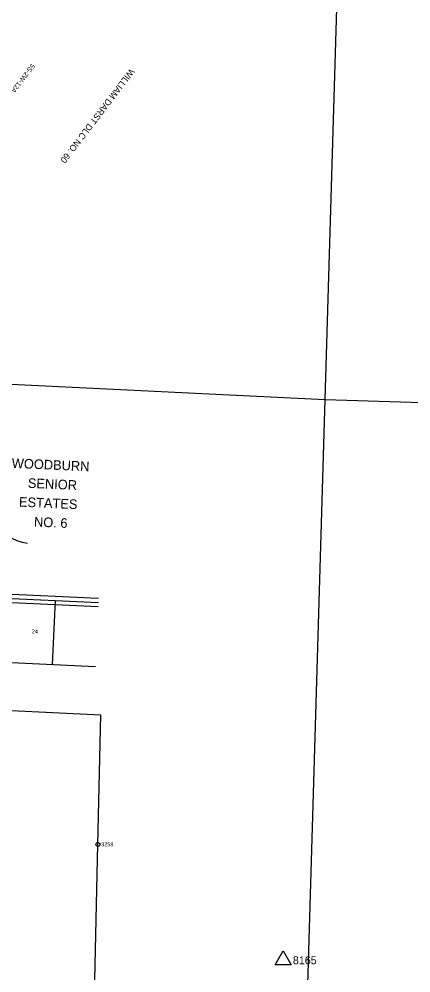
# Model space of a CAD drawing. Extents: x 7581380 to 7602708, y 543740 to 556109.
# Drawn here: x 7590534 to 7591024, y 550879 to 552072 of the extents above; entities that cross this region are included whole.
import ezdxf

# ---------------------------------------------------------------- set-up
doc = ezdxf.new("R2010")
doc.units = 0
for name, color, linetype in [('E_SURV_BNDRY_CROW', 7, 'Continuous'), ('E_SURV_BNDRY_Easement', 7, 'Continuous'), ('E_SURV_BNDRY_GovDLCLineTx', 7, 'Continuous'), ('E_SURV_BNDRY_GovSixSectLine', 7, 'Continuous'), ('E_SURV_BNDRY_Property', 7, 'Continuous'), ('E_SURV_BNDRY_SubdivisionTx', 7, 'Continuous'), ('E_Surv_Bndry_Tax_Lot', 7, 'Continuous'), ('E_SURV_MON_FdMon', 7, 'Continuous'), ('E_SURV_MON_FdMonTx', 7, 'Continuous'), ('E_SURV_NTW_SetNtwPt', 7, 'Continuous'), ('E_SURV_NTW_SetNtwPtTx', 7, 'Continuous')]:
    doc.layers.add(name, color=color, linetype=linetype)

msp = doc.modelspace()

# ---------------------------------------------------------------- linework, layer by layer
at = {"layer": 'E_SURV_BNDRY_CROW'}
for p, q in [((7590420.3, 551272.2), (7590629.5, 551262.4)), ((7590328.9, 551216.5), (7590636.5, 551201.9)), ((7590632.7, 551039.9), (7590636.5, 551201.9))]:
    msp.add_line(p, q, dxfattribs=at)
msp.add_arc((7590549.7, 551466.5), 50.2, 140.2086, 264.2644, dxfattribs=at)
at = {"layer": 'E_SURV_BNDRY_Easement'}
for p, q in [((7590633.5, 551347.3), (7590434.2, 551356.6)), ((7590433.8, 551346.7), (7590633.1, 551337.3))]:
    msp.add_line(p, q, dxfattribs=at)
at = {"layer": 'E_SURV_BNDRY_GovSixSectLine'}
for p, q in [((7588277.4, 551724.3), (7590917, 551595.9)), ((7590917, 551595.9), (7592227.2, 551558.5))]:
    msp.add_line(p, q, dxfattribs=at)
for points in [[(7590917, 551595.9), (7590956.2, 552910)], [(7590878.1, 550287.8), (7590917, 551595.9)]]:
    msp.add_lwpolyline(points, dxfattribs=at)
at = {"layer": 'E_SURV_BNDRY_Property'}
for p, q in [((7590424, 551352.1), (7590633.3, 551342.3)), ((7590576.1, 551264.9), (7590579.8, 551344.8)), ((7590613.5, 550215.1), (7590632.7, 551039.9))]:
    msp.add_line(p, q, dxfattribs=at)
at = {"layer": 'E_SURV_MON_FdMon'}
msp.add_circle((7590632.7, 551039.9), 2.5, dxfattribs=at)
at = {"layer": 'E_SURV_NTW_SetNtwPt'}
for p, q in [((7590854.5, 550889.3), (7590864.5, 550906.7)), ((7590864.5, 550906.7), (7590874.5, 550889.3)), ((7590874.5, 550889.3), (7590854.5, 550889.3)), ((7590864.5, 550895.1), (7590864.5, 550895.1))]:
    msp.add_line(p, q, dxfattribs=at)

# ---------------------------------------------------------------- texts
at = {"layer": 'E_SURV_BNDRY_GovDLCLineTx'}
msp.add_text('WILLIAM DARST DLC NO. 60', height=8, rotation=232.6004, dxfattribs=at).set_placement((7590672.9, 552010.2))
at = {"layer": 'E_SURV_BNDRY_SubdivisionTx'}
for s, height, rotation, p in [('WOODBURN', 12, 357.4657, (7590524.8, 551510.6)), ('SENIOR', 12, 357.4657, (7590544.9, 551485.7)), ('ESTATES', 12, 357.4657, (7590533.8, 551462.2)), ('NO. 6', 12, 357.4657, (7590552.6, 551437.3)), ('24', 5, 358.4657, (7590550, 551303.8))]:
    msp.add_text(s, height=height, rotation=rotation, dxfattribs=at).set_placement(p)
at = {"layer": 'E_Surv_Bndry_Tax_Lot'}
msp.add_text('5S-2W-12A-100', height=6, rotation=232.4684, dxfattribs=at).set_placement((7590549.8, 552016.2))
at = {"layer": 'E_SURV_MON_FdMonTx'}
msp.add_text('3258', height=5, dxfattribs=at).set_placement((7590636.8, 551037.5))
at = {"layer": 'E_SURV_NTW_SetNtwPtTx'}
msp.add_text('8165', height=10, dxfattribs=at).set_placement((7590876.5, 550890.1))

doc.saveas('drawing.dxf')
